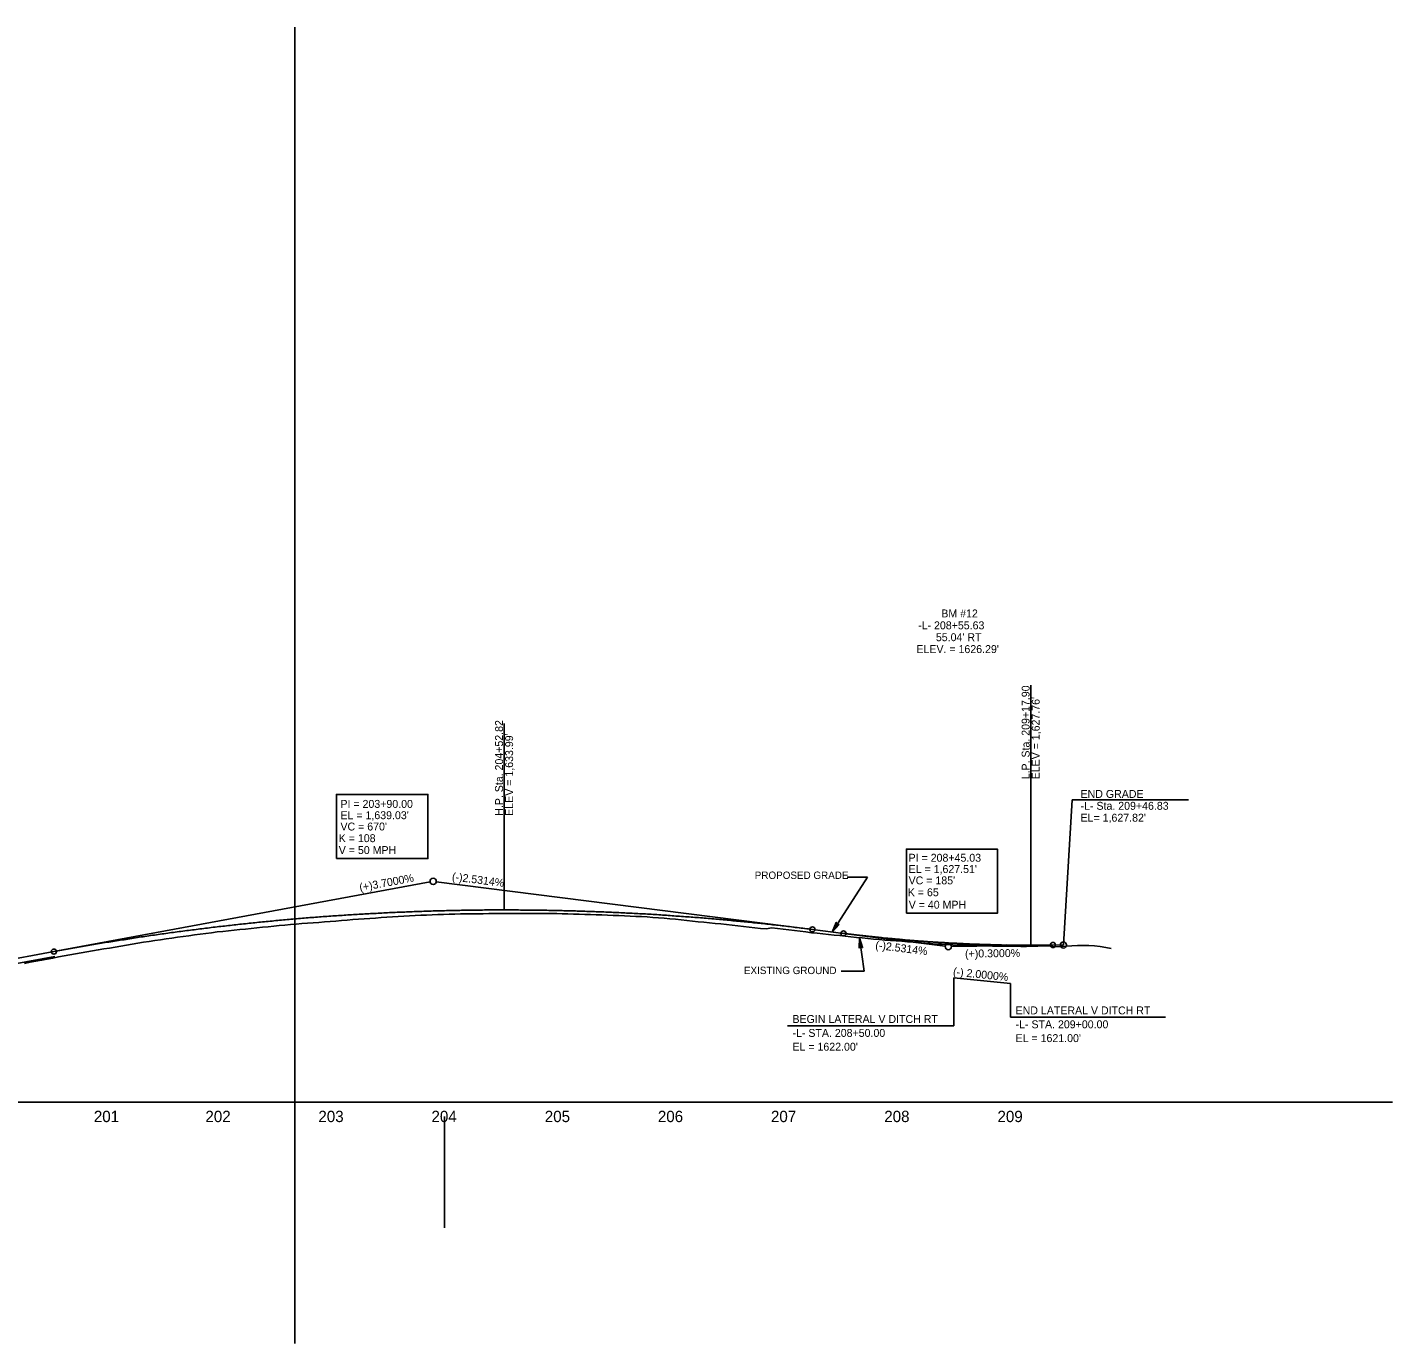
# Model space of a CAD drawing. Extents: x 498575 to 532350, y 405181 to 484585.
# Drawn here: x 524851 to 526057, y 483020 to 484184 of the extents above; entities that cross this region are included whole.
import ezdxf

# ---------------------------------------------------------------- set-up
doc = ezdxf.new("R2010")
doc.units = 0
for name, color, linetype in [('Exist Profile Cell', 7, 'Continuous'), ('Exist Vertical Profile Ground Line', 7, 'Continuous'), ('Exist Vertical Profile Horizontal Axis Label Major', 7, 'Continuous'), ('Prop Grid Mask', 7, 'Continuous'), ('Prop PFL Text', 7, 'Continuous'), ('Prop Vertical Profile Curve Label', 7, 'Continuous'), ('Prop Vertical Profile Ditch Grade Right', 7, 'Continuous'), ('Prop Vertical Profile Ditch Grade Right Label', 7, 'Continuous'), ('Prop Vertical Profile Grade', 7, 'Continuous'), ('Prop Vertical Profile Grade Label', 7, 'Continuous'), ('Prop Vertical Profile Strip Grade', 7, 'Continuous'), ('Prop VPI Label', 7, 'Continuous'), ('Scratch_Level_4', 7, 'Continuous'), ('Scratch_Level_6', 7, 'Continuous'), ('Sheet Profile Grid Minor CELL', 7, 'Continuous')]:
    doc.layers.add(name, color=color, linetype=linetype)

msp = doc.modelspace()

# ---------------------------------------------------------------- linework, layer by layer
at = {"layer": 'Exist Profile Cell'}
msp.add_line((505856.7, 483233.7), (526056.7, 483233.7), dxfattribs=at)
at = {"layer": 'Exist Vertical Profile Ground Line'}
for points in [[(524848.2, 483356.4), (524853.2, 483357.4), (524858.2, 483358.4), (524863.2, 483359.3), (524868.2, 483360.3), (524873.2, 483361.2), (524878.2, 483362.1), (524883.2, 483363), (524888.2, 483363.9), (524893.2, 483364.8), (524898.2, 483365.7), (524903.2, 483366.6), (524908.2, 483367.5), (524913.2, 483368.3), (524918.2, 483369.2), (524923.2, 483370), (524928.2, 483370.9), (524933.2, 483371.7), (524938.2, 483372.6), (524943.2, 483373.5), (524948.2, 483374.3), (524953.2, 483375.1), (524958.2, 483375.9), (524963.2, 483376.6), (524968.2, 483377.4), (524973.2, 483378.1), (524978.2, 483378.8), (524983.2, 483379.5), (524988.2, 483380.3), (524993.2, 483380.9), (524998.2, 483381.6), (525003.2, 483382.3), (525008.2, 483382.9), (525013.2, 483383.5), (525018.2, 483384.2), (525023.2, 483384.7), (525028.2, 483385.2), (525033.2, 483385.8), (525038.2, 483386.3), (525043.2, 483386.8), (525048.2, 483387.4), (525053.2, 483387.9), (525058.2, 483388.4), (525063.2, 483388.9), (525068.2, 483389.4), (525073.2, 483389.9), (525078.2, 483390.3), (525083.2, 483390.7), (525088.2, 483391.2), (525093.2, 483391.6), (525098.2, 483392), (525103.2, 483392.4), (525108.2, 483392.7), (525113.2, 483393.1), (525118.2, 483393.5), (525123.2, 483393.9), (525128.2, 483394.3), (525133.2, 483394.7), (525138.2, 483395.1), (525143.2, 483395.4), (525148.2, 483395.8), (525153.2, 483396.1), (525158.2, 483396.5), (525163.2, 483396.9), (525168.2, 483397.3), (525173.2, 483397.6), (525178.2, 483397.9), (525183.2, 483398.2), (525188.2, 483398.5), (525193.2, 483398.7), (525198.2, 483399), (525203.2, 483399.2), (525208.2, 483399.4), (525213.2, 483399.6), (525218.2, 483399.7), (525223.2, 483399.9), (525228.2, 483400), (525233.2, 483400.1), (525238.2, 483400.2), (525243.2, 483400.2), (525248.2, 483400.3), (525253.2, 483400.3), (525258.2, 483400.4), (525263.2, 483400.4), (525268.2, 483400.5), (525273.2, 483400.5), (525278.2, 483400.5), (525283.2, 483400.5), (525288.2, 483400.5), (525293.2, 483400.5), (525298.2, 483400.5), (525303.2, 483400.5), (525308.2, 483400.5), (525313.2, 483400.5)], [(525313.2, 483400.5), (525318.2, 483400.4), (525323.2, 483400.3), (525328.2, 483400.2), (525333.2, 483400), (525338.2, 483399.9), (525343.2, 483399.7), (525348.2, 483399.6), (525353.2, 483399.4), (525358.2, 483399.3), (525363.2, 483399.1), (525368.2, 483398.9), (525373.2, 483398.7), (525378.2, 483398.5), (525383.2, 483398.3), (525388.2, 483398), (525393.2, 483397.8), (525398.2, 483397.5), (525403.2, 483397.1), (525408.2, 483396.8), (525413.2, 483396.4), (525418.2, 483395.9), (525423.2, 483395.4), (525428.2, 483394.9), (525433.2, 483394.4), (525438.2, 483393.9), (525443.2, 483393.3), (525448.2, 483392.8), (525453.2, 483392.3), (525458.2, 483391.8), (525463.2, 483391.3), (525468.2, 483390.8), (525473.2, 483390.3), (525478.2, 483389.7), (525483.2, 483389.1), (525488.2, 483388.6), (525493.2, 483388), (525498.2, 483387.4), (525503.2, 483387), (525508.2, 483387.8), (525513.2, 483387.2), (525518.2, 483386.6), (525523.2, 483386), (525528.2, 483385.4), (525533.2, 483384.8), (525538.2, 483384.2), (525543.2, 483383.6), (525548.2, 483383.1), (525553.2, 483382.5), (525558.2, 483382), (525563.2, 483381.5), (525568.2, 483381), (525573.2, 483380.5), (525578.2, 483380), (525583.2, 483379.4), (525588.2, 483378.9), (525593.2, 483378.5), (525598.2, 483378), (525603.2, 483377.5), (525608.2, 483377.1), (525613.2, 483376.7), (525618.2, 483376.3), (525623.2, 483376), (525628.2, 483375.6), (525633.2, 483375.2), (525638.2, 483374.8), (525643.2, 483374.4), (525648.2, 483373.9), (525653.2, 483373.5), (525658.2, 483373.3), (525663.2, 483373), (525668.2, 483372.8), (525673.2, 483372.6), (525678.2, 483372.5), (525683.2, 483372.3), (525688.2, 483372.1), (525693.2, 483372), (525698.2, 483371.9), (525703.2, 483371.8), (525708.2, 483371.7), (525713.2, 483371.7), (525718.2, 483371.6), (525723.2, 483371.6), (525728.2, 483371.5), (525733.2, 483371.5), (525738.2, 483371.6), (525743.2, 483371.7), (525748.2, 483371.9), (525753.2, 483371.9), (525758.2, 483371), (525763.2, 483371.3), (525768.2, 483371.7), (525773.2, 483372), (525778.2, 483372.2), (525783.2, 483372.2), (525788.2, 483372.2), (525793.2, 483372), (525798.2, 483371.3), (525803.2, 483370.5), (525807.9, 483369.7)]]:
    msp.add_lwpolyline(points, dxfattribs=at)
at = {"layer": 'Prop Grid Mask'}
for points in [[(525123.6, 483449), (525204.4, 483449), (525204.4, 483505.8), (525123.6, 483505.8)], [(525627.1, 483400.7), (525707.5, 483400.7), (525707.5, 483457.5), (525627.1, 483457.5)]]:
    msp.add_lwpolyline(points, close=True, dxfattribs=at)
at = {"layer": 'Prop PFL Text'}
for p, q in [((525561.7, 483384.1), (525592.8, 483432.6)), ((525592.8, 483432.6), (525574.7, 483432.6)), ((525589.8, 483349.5), (525585.7, 483379.1)), ((525569.5, 483349.5), (525589.8, 483349.5))]:
    msp.add_line(p, q, dxfattribs=at)
for points in [[(525567.8, 483390.8), (525561.7, 483384.1), (525565.2, 483392.6), (525565.9, 483390.7)], [(525585.4, 483370), (525585.7, 483379.1), (525588.5, 483370.4), (525586.8, 483371.3)]]:
    msp.add_lwpolyline(points, close=True, dxfattribs=at)
at = {"layer": 'Prop Vertical Profile Curve Label'}
for centre in [(525544.1, 483386.5), (525571.6, 483383), (524874.1, 483366.9), (525756.6, 483372.7)]:
    msp.add_circle(centre, 2.25, dxfattribs=at)
at = {"layer": 'Prop Vertical Profile Ditch Grade Right'}
msp.add_lwpolyline([(525669.1, 483343.7), (525719.1, 483338.7)], dxfattribs=at)
at = {"layer": 'Prop Vertical Profile Ditch Grade Right Label'}
for p, q in [((525669.1, 483343.7), (525669.1, 483301.2)), ((525719.1, 483338.7), (525719.1, 483308.8)), ((525856.1, 483308.8), (525719.1, 483308.8)), ((525669.1, 483301.2), (525522, 483301.2))]:
    msp.add_line(p, q, dxfattribs=at)
at = {"layer": 'Prop Vertical Profile Grade'}
for p, q in [((525544.1, 483386.5), (525571.6, 483383)), ((525571.6, 483383), (525571.6, 483383)), ((524744.1, 483342.8), (524874.1, 483366.9)), ((525756.6, 483372.7), (525765.9, 483372.8)), ((525756.6, 483372.7), (525765.9, 483372.8))]:
    msp.add_line(p, q, dxfattribs=at)
for points in [[(524874.1, 483366.9), (524887.5, 483369.3), (524900.9, 483371.7), (524914.3, 483374), (524927.7, 483376.1), (524941.1, 483378.2), (524954.5, 483380.3), (524967.9, 483382.2), (524981.3, 483384.1), (524994.7, 483385.8), (525008.1, 483387.5), (525021.5, 483389.1), (525034.9, 483390.6), (525048.3, 483392.1), (525061.7, 483393.4), (525075.1, 483394.7), (525088.5, 483395.9), (525101.9, 483397), (525115.3, 483398), (525128.7, 483398.9), (525142.1, 483399.8), (525155.5, 483400.5), (525168.9, 483401.2), (525182.3, 483401.8), (525195.7, 483402.3), (525209.1, 483402.8), (525222.5, 483403.1), (525235.9, 483403.4), (525249.3, 483403.6), (525262.7, 483403.7), (525276.1, 483403.7), (525289.5, 483403.6), (525302.9, 483403.5), (525316.3, 483403.2), (525329.7, 483402.9), (525343.1, 483402.5), (525356.5, 483402), (525369.9, 483401.5), (525383.3, 483400.8), (525396.7, 483400.1), (525410.1, 483399.3), (525423.5, 483398.3), (525436.9, 483397.4), (525450.3, 483396.3), (525463.7, 483395.1), (525477.1, 483393.9), (525490.5, 483392.6), (525503.9, 483391.2), (525517.3, 483389.7), (525530.7, 483388.1), (525544.1, 483386.5)], [(525571.6, 483383), (525575.3, 483382.5), (525579, 483382.1), (525582.7, 483381.6), (525586.4, 483381.2), (525590.1, 483380.8), (525593.8, 483380.4), (525597.5, 483380), (525601.2, 483379.6), (525604.9, 483379.2), (525608.6, 483378.8), (525612.3, 483378.5), (525616, 483378.1), (525619.7, 483377.8), (525623.4, 483377.5), (525627.1, 483377.1), (525630.8, 483376.8), (525634.5, 483376.5), (525638.2, 483376.2), (525641.9, 483376), (525645.6, 483375.7), (525649.3, 483375.5), (525653, 483375.2), (525656.7, 483375), (525660.4, 483374.8), (525664.1, 483374.5), (525667.8, 483374.3), (525671.5, 483374.2), (525675.2, 483374), (525678.9, 483373.8), (525682.6, 483373.6), (525686.3, 483373.5), (525690, 483373.4), (525693.7, 483373.2), (525697.4, 483373.1), (525701.1, 483373), (525704.8, 483372.9), (525708.5, 483372.8), (525712.2, 483372.7), (525715.9, 483372.7), (525719.6, 483372.6), (525723.3, 483372.6), (525727, 483372.6), (525730.7, 483372.5), (525734.4, 483372.5), (525738.1, 483372.5), (525741.8, 483372.5), (525745.5, 483372.5), (525749.2, 483372.6), (525752.9, 483372.6), (525756.6, 483372.7)]]:
    msp.add_spline(points, degree=3, dxfattribs=at)
at = {"layer": 'Prop Vertical Profile Strip Grade'}
for p, q in [((525737, 483602.4), (525737, 483372.5)), ((525271.9, 483568.4), (525271.9, 483403.7))]:
    msp.add_line(p, q, dxfattribs=at)
at = {"layer": 'Prop VPI Label'}
for p, q in [((525773.6, 483501.1), (525765.9, 483372.8)), ((525773.6, 483501.1), (525876.4, 483501.1)), ((524874.1, 483366.9), (525206.4, 483428.4)), ((525544.1, 483386.5), (525211.8, 483428.5)), ((525571.6, 483383), (525661.4, 483371.6)), ((525756.6, 483372.7), (525666.9, 483371.3))]:
    msp.add_line(p, q, dxfattribs=at)
for centre in [(525209.1, 483428.9), (525765.9, 483372.8), (525765.9, 483372.8), (525664.1, 483371.3)]:
    msp.add_circle(centre, 2.75, dxfattribs=at)
at = {"layer": 'Scratch_Level_4'}
msp.add_line((525086.8, 484183.7), (525086.8, 483020.4), dxfattribs=at)
at = {"layer": 'Scratch_Level_6'}
msp.add_line((524744.9, 483338.5), (524874.9, 483362.6), dxfattribs=at)
at = {"layer": 'Sheet Profile Grid Minor CELL'}
msp.add_line((525219.1, 483221.2), (525219.1, 483122.9), dxfattribs=at)

# ---------------------------------------------------------------- texts
at = {"layer": 'Exist Vertical Profile Horizontal Axis Label Major'}
for s, p in [('201', (524909.4, 483216.2)), ('201', (524909.3, 483216.2)), ('202', (525007.9, 483216.2)), ('202', (525007.9, 483216.2)), ('203', (525107.7, 483216.2)), ('203', (525107.7, 483216.2)), ('204', (525207.6, 483216.2)), ('204', (525207.6, 483216.2)), ('205', (525307.7, 483216.2)), ('205', (525307.7, 483216.2)), ('206', (525407.6, 483216.2)), ('206', (525407.6, 483216.2)), ('207', (525507.5, 483216.2)), ('207', (525507.5, 483216.2)), ('208', (525607.6, 483216.2)), ('208', (525607.6, 483216.2)), ('209', (525707.6, 483216.2)), ('209', (525707.6, 483216.2))]:
    msp.add_text(s, height=10, dxfattribs=at).set_placement(p)
at = {"layer": 'Prop PFL Text'}
for s, height, p in [('BM #12', 7, (525658, 483662.2)), ('-L- 208+55.63', 7, (525637.5, 483651.7)), ("55.04' RT", 7, (525653.2, 483641.2)), ("ELEV. = 1626.29'", 7, (525636, 483630.7)), ('PROPOSED GRADE', 6.516, (525493.2, 483431.1)), ('EXISTING GROUND', 6.516, (525483.6, 483347))]:
    msp.add_text(s, height=height, dxfattribs=at).set_placement(p)
at = {"layer": 'Prop Vertical Profile Curve Label'}
for s, p in [("VC = 670'", (525127.2, 483473.9)), ('V = 50 MPH ', (525125.7, 483453.1)), ('K = 108', (525125.7, 483463.6)), ("VC = 185'", (525629.1, 483426.3)), ('K = 65', (525628.4, 483415.8)), ('V = 40 MPH', (525629.2, 483404.8))]:
    msp.add_text(s, height=7, dxfattribs=at).set_placement(p)
at = {"layer": 'Prop Vertical Profile Ditch Grade Right Label'}
for s, rotation, p in [('(-) 2.0000%', 354.1416, (525668.1, 483345.8)), ('END LATERAL V DITCH RT', 360, (525723.6, 483311.4)), ('BEGIN LATERAL V DITCH RT', 360, (525526.5, 483303.8)), ('-L- STA. 209+00.00', 360, (525723.6, 483299.1)), ('-L- STA. 208+50.00', 360, (525526.5, 483291.5)), ("EL = 1621.00'", 360, (525723.6, 483286.9)), ("EL = 1622.00'", 360, (525526.5, 483279.3))]:
    msp.add_text(s, height=7, rotation=rotation, dxfattribs=at).set_placement(p)
at = {"layer": 'Prop Vertical Profile Grade Label'}
for s, rotation, p in [('(-)2.5314%', 352.7863, (525225.4, 483429.8)), ('(+)3.7000%', 10.4812, (525144.6, 483420)), ('(-)2.5314%', 352.7863, (525599.4, 483369.4)), ('(+)0.3000%', 0.8594, (525679, 483361.5))]:
    msp.add_text(s, height=7, rotation=rotation, dxfattribs=at).set_placement(p)
at = {"layer": 'Prop Vertical Profile Strip Grade'}
for s, p in [('L.P. Sta. 209+17.90', (525736, 483519.1)), ("ELEV = 1,627.76'", (525744.9, 483519.1)), ('H.P. Sta. 204+52.82', (525270.8, 483486.9)), ("ELEV = 1,633.99'", (525279.7, 483486.9))]:
    msp.add_text(s, height=7, rotation=90, dxfattribs=at).set_placement(p)
at = {"layer": 'Prop VPI Label'}
for s, p in [('END GRADE', (525781, 483502.7)), ('PI = 203+90.00', (525127.2, 483493.9)), ('-L- Sta. 209+46.83', (525781, 483492.2)), ("EL = 1,639.03'", (525127.2, 483483.9)), ("EL= 1,627.82'", (525781, 483481.7)), ('PI = 208+45.03', (525629.1, 483446.3)), ("EL = 1,627.51'", (525629.1, 483436.3)), ("EL = 1,627.51'", (525629.1, 483436.3))]:
    msp.add_text(s, height=7, dxfattribs=at).set_placement(p)

doc.saveas('drawing.dxf')
